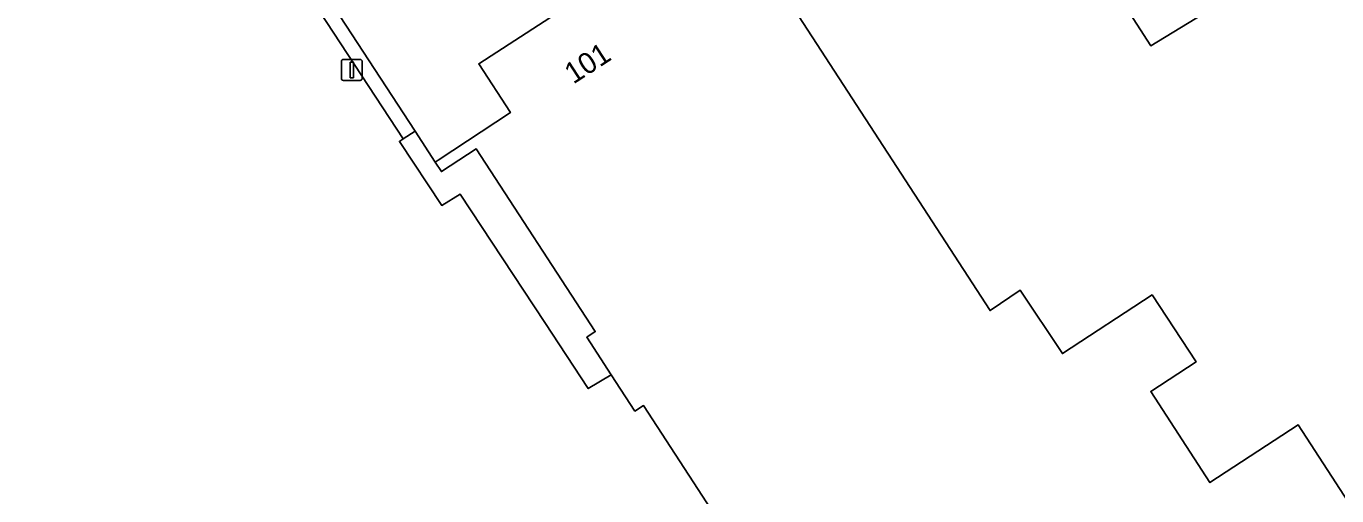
# Model space of a CAD drawing. Extents: x 156061 to 157804, y 383437 to 385640.
# Drawn here: x 156312.5 to 156374.8, y 385424.2 to 385446.5 of the extents above; entities that cross this region are included whole.
import ezdxf

# ---------------------------------------------------------------- set-up
doc = ezdxf.new("R2010")
doc.units = 0
for name, color, linetype in [('IMGEO_Groenvoorziening', 7, 'Continuous'), ('IMGEO_Lichtmast', 7, 'Continuous'), ('IMGEO_Pand', 7, 'Continuous'), ('IMGEO_Pand_nummerreeks', 7, 'Continuous'), ('IMGEO_Parkeervlak_open', 7, 'Continuous'), ('IMGEO_Rijbaan_lokaal_open', 7, 'Continuous'), ('IMGEO_Voetpad_open', 7, 'Continuous')]:
    doc.layers.add(name, color=color, linetype=linetype)

msp = doc.modelspace()

# ---------------------------------------------------------------- linework, layer by layer
at = {"layer": 'IMGEO_Groenvoorziening'}
msp.add_lwpolyline([(156317.547, 385462.129), (156316.945, 385461.751), (156317.186, 385461.382), (156330.427, 385441.19), (156330.985, 385441.559)], close=True, dxfattribs=at)
msp.add_lwpolyline([(156351.509, 385413.653), (156341.841, 385428.524), (156341.425, 385428.262), (156340.295, 385429.992), (156339.21, 385429.331), (156337.146, 385432.464), (156333.122, 385438.573), (156332.253, 385438.03), (156330.247, 385441.071), (156330.427, 385441.19), (156317.186, 385461.382), (156316.945, 385461.751), (156316.628, 385461.551), (156308.21, 385456.258)], dxfattribs=at)
at = {"layer": 'IMGEO_Lichtmast'}
for p, q in [((156327.486, 385444.068), (156327.486, 385444.868)), ((156327.486, 385444.868), (156327.486, 385444.068)), ((156327.586, 385444.968), (156328.376, 385444.968)), ((156328.376, 385444.968), (156327.586, 385444.968)), ((156328.476, 385444.868), (156328.476, 385444.068)), ((156328.476, 385444.068), (156328.476, 385444.868)), ((156328.376, 385443.968), (156327.586, 385443.968)), ((156327.586, 385443.968), (156328.376, 385443.968))]:
    msp.add_line(p, q, dxfattribs=at)
msp.add_lwpolyline([(156327.906, 385444.843), (156328.056, 385444.843), (156328.056, 385444.093), (156327.906, 385444.093), (156327.906, 385444.843)], dxfattribs=at)
for centre, start, end in [((156327.586, 385444.868), 90, 180), ((156327.586, 385444.868), 90, 180), ((156328.376, 385444.868), 0, 90), ((156328.376, 385444.868), 360, 90), ((156327.586, 385444.068), 180, 270), ((156327.586, 385444.068), 180, 270), ((156328.376, 385444.068), 270, 0), ((156328.376, 385444.068), 270, 0)]:
    msp.add_arc(centre, 0.1, start, end, dxfattribs=at)
at = {"layer": 'IMGEO_Pand'}
for points in [[(156341.394, 385449.556), (156334.01, 385444.763), (156335.512, 385442.442), (156332.089, 385440.188), (156331.943, 385440.092), (156332.234, 385439.642), (156333.882, 385440.727), (156339.546, 385432.036), (156339.136, 385431.768), (156340.295, 385429.992), (156341.425, 385428.262), (156341.841, 385428.524), (156351.509, 385413.653)], [(156384.822, 385409.281), (156372.927, 385427.602), (156368.728, 385424.868), (156365.924, 385429.194), (156368.074, 385430.595), (156365.984, 385433.784), (156361.723, 385430.995), (156359.724, 385434.004), (156358.292, 385433.036), (156347.517, 385449.635)]]:
    msp.add_lwpolyline(points, dxfattribs=at)
at = {"layer": 'IMGEO_Parkeervlak_open'}
for points in [[(156317.547, 385462.129), (156330.985, 385441.559), (156331.943, 385440.092), (156332.089, 385440.188), (156335.512, 385442.442), (156334.01, 385444.763), (156341.394, 385449.556)], [(156358.438, 385457.213), (156365.921, 385445.613), (156379.577, 385453.937)]]:
    msp.add_lwpolyline(points, dxfattribs=at)
at = {"layer": 'IMGEO_Rijbaan_lokaal_open'}
msp.add_lwpolyline([(156378.466, 385446.992), (156377.576, 385448.369), (156381.366, 385450.749), (156379.577, 385453.937), (156365.921, 385445.613), (156358.438, 385457.213), (156358.242, 385457.212), (156358.192, 385457.177), (156357.947, 385457.003), (156357.702, 385456.83), (156353.963, 385454.187), (156348.922, 385451.157), (156349.216, 385450.712), (156347.517, 385449.635), (156358.292, 385433.036), (156359.724, 385434.004), (156361.723, 385430.995), (156365.984, 385433.784), (156368.074, 385430.595), (156365.924, 385429.194), (156368.728, 385424.868), (156372.927, 385427.602), (156384.822, 385409.281)], dxfattribs=at)
at = {"layer": 'IMGEO_Voetpad_open'}
msp.add_lwpolyline([(156333.882, 385440.727), (156332.234, 385439.642), (156331.943, 385440.092), (156330.985, 385441.559), (156330.427, 385441.19), (156330.247, 385441.071), (156332.253, 385438.03), (156333.122, 385438.573), (156337.146, 385432.464), (156339.21, 385429.331), (156340.295, 385429.992), (156339.136, 385431.768), (156339.546, 385432.036)], close=True, dxfattribs=at)

# ---------------------------------------------------------------- texts
at = {"layer": 'IMGEO_Pand_nummerreeks'}
msp.add_text('101', height=1, rotation=32.98785, dxfattribs=at).set_placement((156338.504, 385443.77))

doc.saveas('drawing.dxf')
